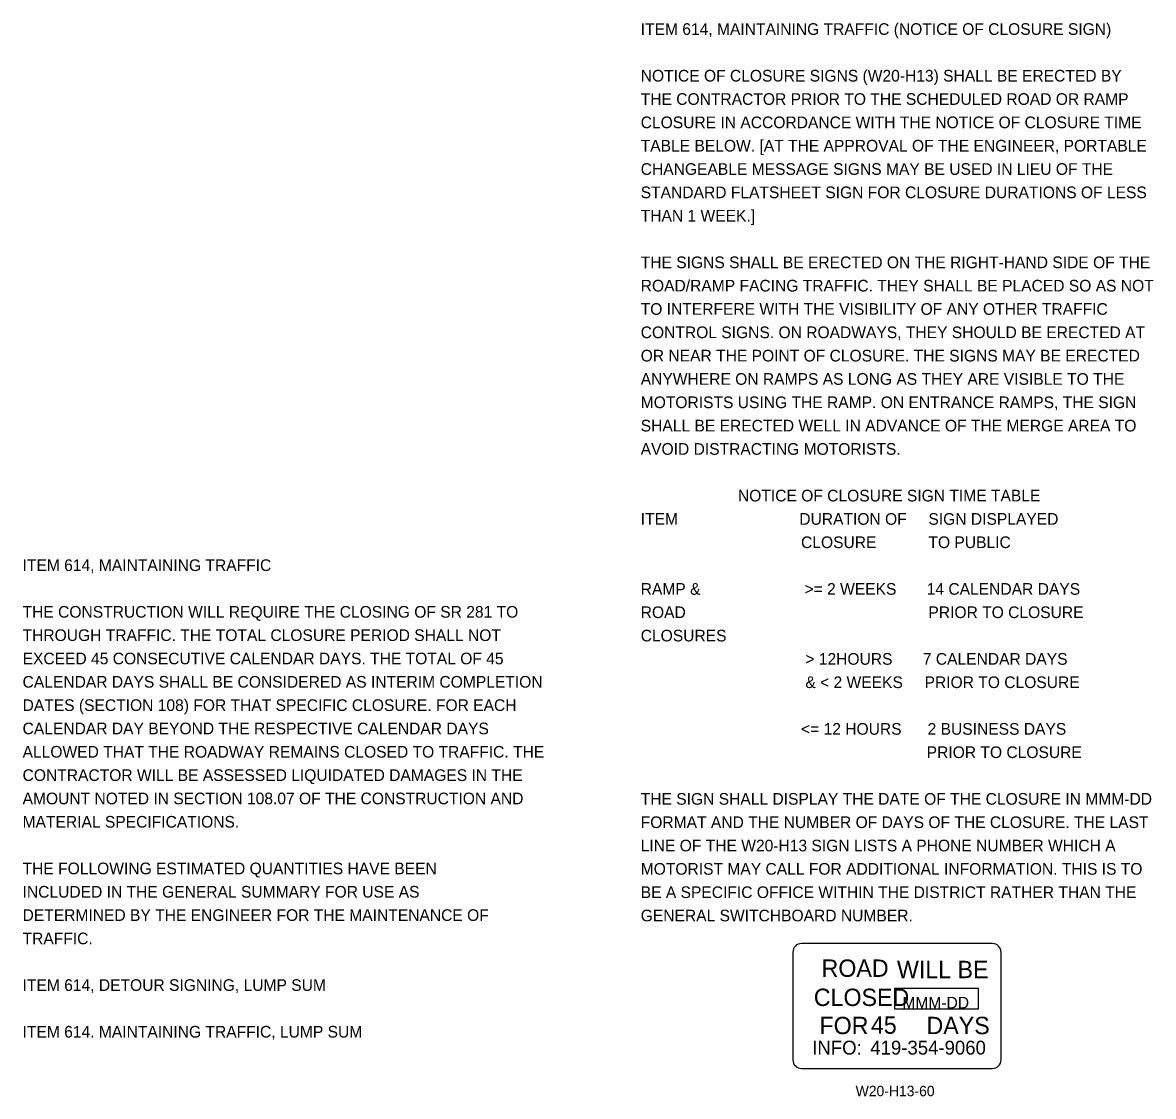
# Model space of a CAD drawing. Extents: x -7.7 to 42.4, y 0 to 36.3.
# Drawn here: x 2.4 to 15.97, y 23.42 to 36.3 of the extents above; entities that cross this region are included whole.
import ezdxf

# ---------------------------------------------------------------- set-up
doc = ezdxf.new("R2010")
doc.units = 0
for name, color, linetype in [('SH_Text', 7, 'Continuous'), ('SN_P_Signs', 7, 'Continuous'), ('SN_P_Text', 7, 'Continuous')]:
    doc.layers.add(name, color=color, linetype=linetype)

msp = doc.modelspace()

# ---------------------------------------------------------------- linework, layer by layer
at = {"layer": 'SH_Text'}
msp.add_lwpolyline([(12.871, 24.713), (13.871, 24.713), (13.871, 24.463), (12.871, 24.463)], close=True, dxfattribs=at)
at = {"layer": 'SN_P_Signs'}
for p, q in [((14.042, 25.25), (11.75, 25.25)), ((11.646, 25.146), (11.646, 23.854)), ((14.146, 23.854), (14.146, 25.146)), ((11.75, 23.75), (14.042, 23.75))]:
    msp.add_line(p, q, dxfattribs=at)
for centre, start, end in [((11.75, 25.146), 90, 180), ((14.042, 25.146), 0, 90), ((11.75, 23.854), 180, 270), ((14.042, 23.854), 270, 360)]:
    msp.add_arc(centre, 0.104, start, end, dxfattribs=at)

# ---------------------------------------------------------------- texts
at = {"layer": 'SH_Text'}
for s, p in [('ITEM 614, MAINTAINING TRAFFIC (NOTICE OF CLOSURE SIGN)', (9.82, 36.156)), ('NOTICE OF CLOSURE SIGNS (W20-H13) SHALL BE ERECTED BY', (9.82, 35.596)), ('THE CONTRACTOR PRIOR TO THE SCHEDULED ROAD OR RAMP', (9.82, 35.316)), ('CLOSURE IN ACCORDANCE WITH THE NOTICE OF CLOSURE TIME', (9.82, 35.036)), ('TABLE BELOW. [AT THE APPROVAL OF THE ENGINEER, PORTABLE', (9.82, 34.756)), ('CHANGEABLE MESSAGE SIGNS MAY BE USED IN LIEU OF THE', (9.82, 34.476)), ('STANDARD FLATSHEET SIGN FOR CLOSURE DURATIONS OF LESS', (9.82, 34.196)), ('THAN 1 WEEK.]', (9.82, 33.916)), ('THE SIGNS SHALL BE ERECTED ON THE RIGHT-HAND SIDE OF THE', (9.82, 33.356)), ('ROAD/RAMP FACING TRAFFIC. THEY SHALL BE PLACED SO AS NOT', (9.82, 33.076)), ('TO INTERFERE WITH THE VISIBILITY OF ANY OTHER TRAFFIC', (9.82, 32.796)), ('CONTROL SIGNS. ON ROADWAYS, THEY SHOULD BE ERECTED AT', (9.82, 32.516)), ('OR NEAR THE POINT OF CLOSURE. THE SIGNS MAY BE ERECTED', (9.82, 32.236)), ('ANYWHERE ON RAMPS AS LONG AS THEY ARE VISIBLE TO THE', (9.82, 31.956)), ('MOTORISTS USING THE RAMP. ON ENTRANCE RAMPS, THE SIGN', (9.82, 31.676)), ('SHALL BE ERECTED WELL IN ADVANCE OF THE MERGE AREA TO', (9.82, 31.396)), ('AVOID DISTRACTING MOTORISTS.', (9.82, 31.116)), ('NOTICE OF CLOSURE SIGN TIME TABLE', (10.987, 30.556)), ('ITEM                            DURATION OF     SIGN DISPLAYED', (9.82, 30.276)), ('                                     CLOSURE            TO PUBLIC', (9.82, 29.996)), ('ITEM 614, MAINTAINING TRAFFIC', (2.4, 29.721)), ('RAMP &                        >= 2 WEEKS       14 CALENDAR DAYS', (9.82, 29.436)), ('THE CONSTRUCTION WILL REQUIRE THE CLOSING OF SR 281 TO', (2.4, 29.161)), ('ROAD                                                        PRIOR TO CLOSURE', (9.82, 29.156)), ('THROUGH TRAFFIC. THE TOTAL CLOSURE PERIOD SHALL NOT', (2.4, 28.881)), ('CLOSURES', (9.82, 28.876)), ('EXCEED 45 CONSECUTIVE CALENDAR DAYS. THE TOTAL OF 45', (2.4, 28.601)), ('                                      > 12HOURS       7 CALENDAR DAYS', (9.82, 28.596)), ('CALENDAR DAYS SHALL BE CONSIDERED AS INTERIM COMPLETION', (2.4, 28.321)), ('                                      & < 2 WEEKS     PRIOR TO CLOSURE', (9.82, 28.316)), ('DATES (SECTION 108) FOR THAT SPECIFIC CLOSURE. FOR EACH', (2.4, 28.041)), ('CALENDAR DAY BEYOND THE RESPECTIVE CALENDAR DAYS', (2.4, 27.761)), ('                                     <= 12 HOURS      2 BUSINESS DAYS', (9.82, 27.756)), ('ALLOWED THAT THE ROADWAY REMAINS CLOSED TO TRAFFIC. THE', (2.4, 27.481)), ('                                                                  PRIOR TO CLOSURE', (9.82, 27.476)), ('CONTRACTOR WILL BE ASSESSED LIQUIDATED DAMAGES IN THE', (2.4, 27.201)), ('AMOUNT NOTED IN SECTION 108.07 OF THE CONSTRUCTION AND', (2.4, 26.921)), ('THE SIGN SHALL DISPLAY THE DATE OF THE CLOSURE IN MMM-DD', (9.82, 26.916)), ('MATERIAL SPECIFICATIONS.', (2.4, 26.641)), ('FORMAT AND THE NUMBER OF DAYS OF THE CLOSURE. THE LAST', (9.82, 26.636)), ('LINE OF THE W20-H13 SIGN LISTS A PHONE NUMBER WHICH A', (9.82, 26.356)), ('THE FOLLOWING ESTIMATED QUANTITIES HAVE BEEN', (2.4, 26.081)), ('MOTORIST MAY CALL FOR ADDITIONAL INFORMATION. THIS IS TO', (9.82, 26.076)), ('INCLUDED IN THE GENERAL SUMMARY FOR USE AS', (2.4, 25.801)), ('BE A SPECIFIC OFFICE WITHIN THE DISTRICT RATHER THAN THE', (9.82, 25.796)), ('DETERMINED BY THE ENGINEER FOR THE MAINTENANCE OF', (2.4, 25.521)), ('GENERAL SWITCHBOARD NUMBER.', (9.82, 25.516)), ('TRAFFIC.', (2.4, 25.241)), ('ITEM 614, DETOUR SIGNING, LUMP SUM', (2.4, 24.681)), ('MMM-DD', (12.961, 24.47)), ('ITEM 614. MAINTAINING TRAFFIC, LUMP SUM', (2.4, 24.121))]:
    msp.add_text(s, height=0.14, dxfattribs=at).set_placement(p)
at = {"layer": 'SN_P_Signs'}
for s, height, p in [('ROAD', 0.2083, (11.991, 24.85)), ('WILL BE', 0.2083, (12.896, 24.834)), ('CLOSED', 0.2083, (11.898, 24.5)), ('FOR         DAYS', 0.20833, (11.966, 24.162)), ('45', 0.2083, (12.583, 24.167)), ('INFO:', 0.1666, (11.879, 23.917)), ('419-354-9060', 0.16658, (12.576, 23.917))]:
    msp.add_text(s, height=height, dxfattribs=at).set_placement(p)
at = {"layer": 'SN_P_Text'}
msp.add_text('W20-H13-60', height=0.125, dxfattribs=at).set_placement((12.4, 23.417))

doc.saveas('drawing.dxf')
